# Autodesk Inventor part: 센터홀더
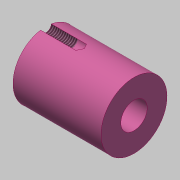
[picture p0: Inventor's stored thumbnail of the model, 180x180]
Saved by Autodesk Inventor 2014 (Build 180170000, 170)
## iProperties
Created: 2019-10
Part Number: 센터홀더
Material: 강철, 연강
Document SubType Name: Modeling
Designer: mduedu
Density: 1 g/cm^3
Appearance: Pink
Author: mduedu
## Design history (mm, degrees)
sketch "스케치1"
  geometry: L1 (0, 0)-(20, 0); L2 (12, -3)-(20, -3); L3 (20, -3)-(20, -7.5); L4 (20, -7.5)-(0, -7.5); L5 (0, -7.5)-(0, -4.127); L6 (0, -4.127)-(12, -3.751); L7 (12, -3.751)-(12, -3)
  constraints: 14 end point, 2 horizontal, 2 parallel, 2 perpendicular, 2 vertical alignment
  dimensions: "d0" = 20 distance of L1.start L1.end; "d1" = 6 diameter of L2 L1; "d2" = 12 distance between parallel lines of L5 L7; "d3" = 7.502 diameter of L6.end L1; "d4" = 8.254 diameter of L5.end L1; "d5" = 15 diameter of L4 L1
revolve "회전1" sketch "스케치1" stored, may be unused: angle "d6" = 90 deg
sketch "스케치2"
  geometry: 3 further points
  constraints: 2 vertical alignment, 1 other
hole "구멍1" sketch "스케치2" at (0, 7.5) diameter "d7" = 2.459; stored, may be unused: countersink angle "d11" = 90 deg, drill point angle "d13" = 118 deg; dims "d8" = 6, "d9" = 4, "d10" = 2, "d12" = 8
node "솔리드1"
